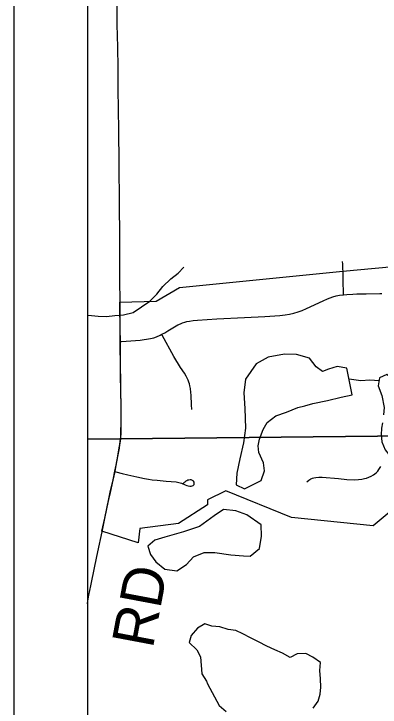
# Model space of a CAD drawing. Extents: x 0 to 34, y 0 to 22.
# Drawn here: x 2 to 2.498, y 17.124 to 18.065 of the extents above; entities that cross this region are included whole.
import ezdxf

# ---------------------------------------------------------------- set-up
doc = ezdxf.new("R2010")
doc.units = 0
for name, color, linetype in [('GM_X_City_Street', 7, 'Continuous'), ('GM_X_Corporation', 7, 'Continuous'), ('GM_X_County_Road', 7, 'Continuous'), ('GM_X_County_Road_Text', 7, 'Continuous'), ('GM_X_Minor_Lake', 7, 'Continuous'), ('GM_X_Minor_River', 7, 'Continuous'), ('SH_Data', 7, 'Continuous')]:
    doc.layers.add(name, color=color, linetype=linetype)

msp = doc.modelspace()

# ---------------------------------------------------------------- linework, layer by layer
at = {"layer": 'GM_X_City_Street'}
for points in [[(2.14421, 17.67336), (2.14392, 17.70496), (2.14378, 17.76337), (2.14345, 17.80629), (2.14302, 17.86276), (2.14253, 17.90741), (2.14179, 17.96331), (2.14154, 17.99181), (2.14102, 18.01996), (2.14045, 18.05066), (2.14016, 18.1184)], [(2.44713, 17.71525), (2.44698, 17.71913), (2.44676, 17.7253), (2.44628, 17.72917)], [(2.44764, 17.68395), (2.4476, 17.69115), (2.44757, 17.69715), (2.44748, 17.70119), (2.44739, 17.70471), (2.44713, 17.71525)], [(2.14474, 17.62019), (2.14638, 17.62032), (2.16502, 17.62168), (2.17163, 17.62236), (2.17712, 17.62296), (2.18027, 17.62342), (2.18583, 17.62449), (2.18997, 17.62556), (2.19355, 17.62674), (2.19853, 17.62884), (2.20099, 17.63013), (2.20511, 17.6323), (2.20914, 17.63484), (2.22296, 17.64282), (2.22634, 17.64454), (2.22929, 17.64569), (2.23217, 17.64659), (2.23497, 17.64733), (2.23876, 17.64807), (2.24352, 17.64881), (2.24969, 17.64946), (2.27552, 17.65118), (2.31343, 17.65311), (2.34112, 17.65452), (2.35463, 17.65529), (2.36147, 17.65575), (2.36861, 17.65656), (2.37438, 17.65767), (2.38055, 17.65895), (2.38622, 17.66051), (2.39154, 17.66248), (2.39772, 17.66503), (2.42019, 17.6756), (2.42595, 17.67818), (2.43326, 17.68106), (2.43781, 17.68242), (2.44214, 17.68327), (2.44764, 17.68395), (2.45224, 17.68435), (2.46026, 17.68462), (2.46586, 17.68491), (2.47854, 17.68517), (2.49712, 17.6857), (2.49978, 17.68575)], [(2.14474, 17.62019), (2.14447, 17.63705), (2.1444, 17.64865), (2.14435, 17.65667), (2.14421, 17.67336)], [(2.24188, 17.52791), (2.24148, 17.53447), (2.24068, 17.54739), (2.24029, 17.5511), (2.23976, 17.55639), (2.23904, 17.56032), (2.23843, 17.56273), (2.23766, 17.56526), (2.23668, 17.56791), (2.23547, 17.57048), (2.23395, 17.57332), (2.23159, 17.5773), (2.22655, 17.58516), (2.21736, 17.60018), (2.20166, 17.62892), (2.20099, 17.63013)], [(2.39811, 17.42965), (2.4008, 17.43222), (2.40321, 17.43364), (2.4056, 17.43471), (2.40748, 17.4352), (2.40999, 17.43566), (2.41431, 17.43594), (2.41866, 17.436), (2.4409, 17.43417), (2.45231, 17.43296), (2.46243, 17.43254), (2.46834, 17.43292), (2.47276, 17.43346), (2.47623, 17.43407), (2.47899, 17.43472), (2.48216, 17.43591), (2.4853, 17.4374), (2.4885, 17.4392), (2.4921, 17.44177), (2.49426, 17.44404), (2.49598, 17.44651), (2.49834, 17.45071)], [(2.13747, 17.44366), (2.13863, 17.44336), (2.14727, 17.44106), (2.15499, 17.43917), (2.16725, 17.43644), (2.17742, 17.43446), (2.18296, 17.43342), (2.18797, 17.43256), (2.19449, 17.43189), (2.20679, 17.43089), (2.22046, 17.42956), (2.22432, 17.42893), (2.22786, 17.42785), (2.23268, 17.42591), (2.23484, 17.42495), (2.23697, 17.42418), (2.23904, 17.4238), (2.24094, 17.42393), (2.24232, 17.42421), (2.24346, 17.42478), (2.24426, 17.42548), (2.24474, 17.42623), (2.245, 17.42716), (2.24506, 17.42811), (2.24475, 17.42939), (2.24413, 17.43047), (2.24336, 17.4312), (2.24262, 17.43173), (2.24172, 17.43214), (2.24065, 17.43235), (2.23944, 17.43238), (2.23765, 17.43215), (2.23641, 17.43182), (2.23505, 17.43124), (2.23377, 17.43046), (2.2323, 17.42951), (2.23138, 17.42879), (2.22995, 17.42737)]]:
    msp.add_lwpolyline(points, dxfattribs=at)
at = {"layer": 'GM_X_Corporation'}
for points in [[(2.1, 20.9), (2.1, 17.48755), (2.14492, 17.48819), (2.14512, 17.49067), (2.14541, 17.49632), (2.14567, 17.5112), (2.14564, 17.5286), (2.14513, 17.55769), (2.14496, 17.56944), (2.14479, 17.58556), (2.14458, 17.61777), (2.14453, 17.62075), (2.14427, 17.6376), (2.14419, 17.6492), (2.14414, 17.65723), (2.144, 17.67392), (2.19324, 17.67521), (2.22491, 17.69348), (2.44692, 17.7158), (2.60303, 17.73026)], [(2.1, 20.9), (2.1, 17.48755), (2.14492, 17.48819), (2.58119, 17.49248), (2.63524, 17.49292), (3.04564, 17.48944), (3.4708, 17.4915), (3.58006, 17.49243), (3.7119, 17.4934), (4.71799, 17.49624)], [(2.63524, 17.49292), (2.4881, 17.36991), (2.37721, 17.38137), (2.28804, 17.41743), (2.263, 17.40524), (2.263, 17.3986), (2.22358, 17.37303), (2.17092, 17.36659), (2.16885, 17.34699), (2.11972, 17.36258), (2.12343, 17.3806), (2.12615, 17.39363), (2.12894, 17.4065), (2.13104, 17.41578), (2.1348, 17.43238), (2.13727, 17.44421), (2.139, 17.45247), (2.14123, 17.4647), (2.14314, 17.47613), (2.14381, 17.48045), (2.14492, 17.48819), (2.14512, 17.49067), (2.14541, 17.49632), (2.14567, 17.5112), (2.14564, 17.5286), (2.14513, 17.55769), (2.14496, 17.56944), (2.14479, 17.58556), (2.14458, 17.61777), (2.14453, 17.62075), (2.14427, 17.6376), (2.14419, 17.6492), (2.14414, 17.65723), (2.144, 17.67392), (2.19324, 17.67521), (2.22491, 17.69348), (2.44692, 17.7158), (2.60303, 17.73026)], [(4.71799, 17.49624), (3.7119, 17.4934), (3.58006, 17.49243), (3.4708, 17.4915), (3.04564, 17.48944), (2.63524, 17.49292), (2.58119, 17.49248), (2.14492, 17.48819), (2.1, 17.48755), (2.1, 14.1), (5.03982, 14.1)]]:
    msp.add_lwpolyline(points, dxfattribs=at)
at = {"layer": 'GM_X_County_Road'}
for points in [[(2.14513, 17.48764), (2.14533, 17.49012), (2.14561, 17.49577), (2.14588, 17.51065), (2.14584, 17.52805), (2.14533, 17.55714), (2.14516, 17.56889), (2.14499, 17.585), (2.14478, 17.61722), (2.14474, 17.62019)], [(2.13747, 17.44366), (2.1392, 17.45192), (2.14144, 17.46415), (2.14335, 17.47558), (2.14401, 17.4799), (2.14513, 17.48764)], [(2.11993, 17.36203), (2.12364, 17.38004), (2.12636, 17.39307), (2.12914, 17.40594), (2.13125, 17.41523), (2.13501, 17.43182), (2.13747, 17.44366)], [(2.1, 17.26413), (2.10014, 17.2649), (2.10106, 17.27044), (2.10206, 17.27591), (2.10477, 17.28832), (2.11016, 17.31505), (2.11391, 17.33469), (2.11993, 17.36203)]]:
    msp.add_lwpolyline(points, dxfattribs=at)
at = {"layer": 'GM_X_Minor_Lake'}
for p, q in [((2.45953, 17.54772), (2.45244, 17.58407)), ((2.27309, 17.33391), (2.29467, 17.33048)), ((2.26313, 17.15522), (2.27887, 17.12614))]:
    msp.add_line(p, q, dxfattribs=at)
for points in [[(2.45244, 17.58407), (2.43917, 17.58662), (2.42747, 17.58274), (2.41916, 17.57964), (2.41079, 17.58602), (2.40161, 17.59771), (2.38416, 17.60288), (2.36751, 17.60313), (2.34559, 17.59917), (2.32901, 17.58994), (2.31479, 17.56935), (2.31228, 17.55075), (2.31358, 17.52915), (2.31455, 17.50261), (2.31205, 17.48287), (2.30692, 17.46121), (2.30291, 17.44146), (2.3019, 17.4259), (2.31329, 17.4203), (2.33592, 17.43148), (2.34035, 17.44478), (2.33913, 17.45577), (2.33259, 17.46975), (2.33176, 17.47885), (2.33359, 17.48758), (2.33878, 17.5009), (2.34401, 17.51042), (2.35605, 17.51923), (2.37039, 17.52427), (2.38586, 17.53084), (2.3953, 17.53319), (2.40626, 17.53593), (2.42628, 17.54026), (2.44479, 17.54495), (2.45953, 17.54772)], [(2.50068, 17.50973), (2.49962, 17.50252), (2.49893, 17.49379), (2.49977, 17.48394), (2.50439, 17.47335), (2.50936, 17.46695), (2.51732, 17.46587), (2.52523, 17.4701), (2.53162, 17.47698), (2.54096, 17.4926), (2.54462, 17.50818), (2.54749, 17.5283), (2.53751, 17.54642), (2.5192, 17.56524), (2.50663, 17.57539), (2.49682, 17.57114), (2.49501, 17.56013), (2.50004, 17.54689), (2.50319, 17.53061), (2.50216, 17.52061)], [(2.29467, 17.33048), (2.31173, 17.32928), (2.32082, 17.32897), (2.33361, 17.33931), (2.3365, 17.35601), (2.33601, 17.37118), (2.3166, 17.38506), (2.30142, 17.39025), (2.28475, 17.39202), (2.27195, 17.38358), (2.25238, 17.36902), (2.23048, 17.36202), (2.20518, 17.35462), (2.19159, 17.35034), (2.18219, 17.34231), (2.18568, 17.33096), (2.19295, 17.32115), (2.20514, 17.31101), (2.22143, 17.30886), (2.23461, 17.31768), (2.24399, 17.32799), (2.25833, 17.33379), (2.27309, 17.33391)], [(2.40645, 17.1222), (2.41319, 17.13173), (2.41614, 17.14161), (2.4172, 17.1511), (2.41636, 17.16209), (2.41552, 17.17346), (2.41656, 17.18447), (2.40629, 17.19159), (2.39679, 17.19645), (2.38506, 17.19636), (2.37526, 17.19135), (2.36499, 17.19696), (2.35436, 17.20143), (2.34372, 17.20666), (2.33232, 17.21263), (2.32131, 17.21786), (2.31104, 17.22347), (2.30155, 17.22795), (2.29131, 17.22938), (2.27993, 17.23271), (2.26895, 17.23376), (2.25947, 17.23672), (2.24967, 17.23096), (2.24066, 17.22103), (2.23809, 17.21153), (2.24839, 17.20175), (2.25376, 17.19193), (2.25545, 17.16919), (2.26159, 17.159), (2.26313, 17.15522)], [(2.27887, 17.12614), (2.2884, 17.11787)]]:
    msp.add_lwpolyline(points, dxfattribs=at)
at = {"layer": 'GM_X_Minor_River'}
for points in [[(2.1, 17.65603), (2.10102, 17.65607), (2.11466, 17.65466), (2.12564, 17.65436), (2.13698, 17.65559), (2.14909, 17.65644), (2.16193, 17.65995), (2.1736, 17.66763), (2.18452, 17.67492), (2.19429, 17.68486), (2.20253, 17.69516), (2.21305, 17.70548), (2.22321, 17.71314), (2.23072, 17.72116)], [(2.49611, 17.56679), (2.4836, 17.56762), (2.47149, 17.56715), (2.45533, 17.56923)]]:
    msp.add_lwpolyline(points, dxfattribs=at)
at = {"layer": 'SH_Data'}
for p, q in [((2, 21), (2, 14)), ((2.1, 20.9), (2.1, 14.1))]:
    msp.add_line(p, q, dxfattribs=at)

# ---------------------------------------------------------------- texts
at = {"layer": 'GM_X_County_Road_Text'}
msp.add_text('RD', height=0.056818, rotation=79.32444, dxfattribs=at).set_placement((2.18862, 17.20216))

doc.saveas('drawing.dxf')
